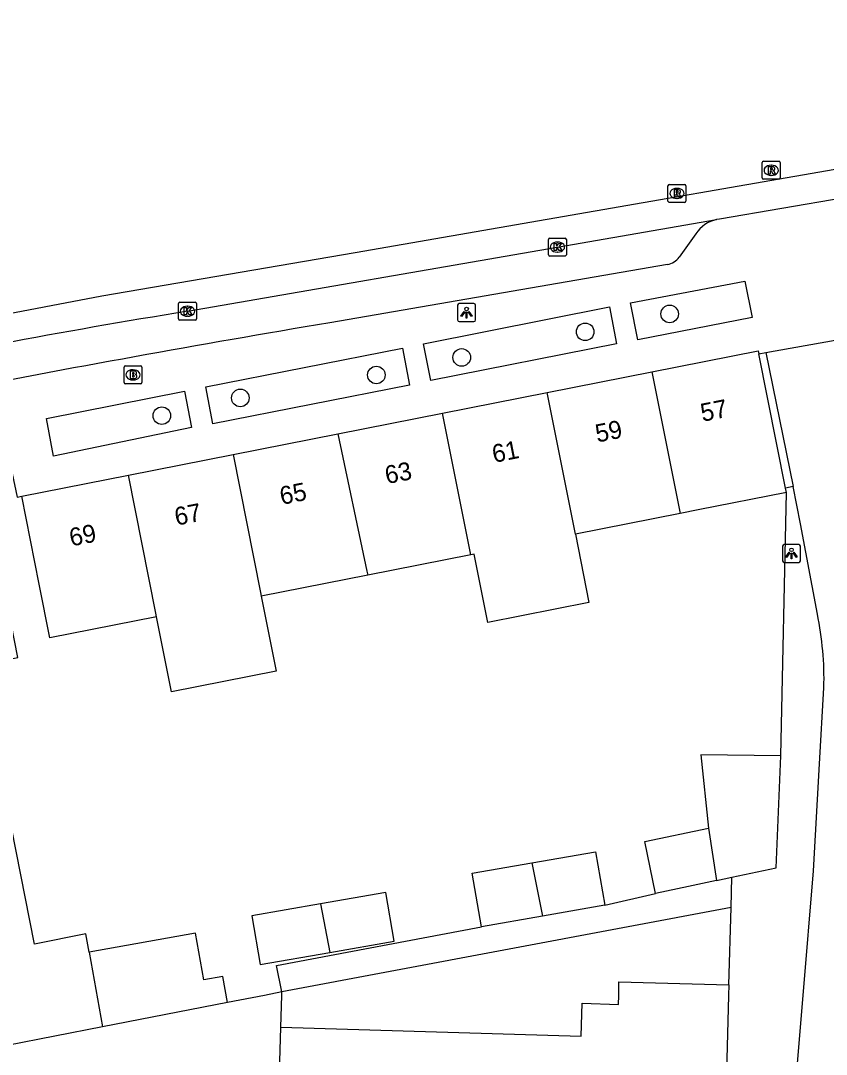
# Model space of a CAD drawing. Extents: x 159053 to 160041, y 380450 to 381422.
# Drawn here: x 159374 to 159418.9, y 381246.7 to 381304.3 of the extents above; entities that cross this region are included whole.
import ezdxf

# ---------------------------------------------------------------- set-up
doc = ezdxf.new("R2010")
doc.units = 0
for name, color, linetype in [('IMGEO_Boom', 7, 'Continuous'), ('IMGEO_Brandkraan', 7, 'Continuous'), ('IMGEO_Kolk', 7, 'Continuous'), ('IMGEO_Lichtpunt', 7, 'Continuous'), ('IMGEO_Muur', 7, 'Continuous'), ('IMGEO_Pand', 7, 'Continuous'), ('IMGEO_Pand_nummerreeks', 7, 'Continuous'), ('IMGEO_Rijbaan_lokaal_gesloten', 7, 'Continuous'), ('IMGEO_Rijbaan_lokaal_open', 7, 'Continuous'), ('IMGEO_Rioolput', 7, 'Continuous'), ('IMGEO_Voetpad_open', 7, 'Continuous')]:
    doc.layers.add(name, color=color, linetype=linetype)

msp = doc.modelspace()

# ---------------------------------------------------------------- linework, layer by layer
at = {"layer": 'IMGEO_Boom'}
for centre in [(159410.139, 381287.939), (159405.431, 381286.943), (159398.564, 381285.517), (159393.813, 381284.541), (159386.237, 381283.263), (159381.873, 381282.275)]:
    msp.add_circle(centre, 0.489, dxfattribs=at)
at = {"layer": 'IMGEO_Brandkraan'}
for p, q in [((159379.765, 381284.122), (159379.765, 381284.974)), ((159379.84, 381285.048), (159380.692, 381285.048)), ((159380.766, 381284.974), (159380.766, 381284.122)), ((159380.253, 381284.828), (159380.278, 381284.828)), ((159380.692, 381284.048), (159379.84, 381284.048)), ((159380.276, 381284.268), (159380.251, 381284.268))]:
    msp.add_line(p, q, dxfattribs=at)
for points in [[(159379.765, 381284.122), (159379.765, 381284.974)], [(159379.84, 381285.048), (159380.692, 381285.048)], [(159380.766, 381284.974), (159380.766, 381284.122)], [(159380.113, 381284.748), (159380.113, 381284.348), (159380.326, 381284.348)], [(159380.344, 381284.748), (159380.113, 381284.748)], [(159380.292, 381284.667), (159380.238, 381284.667), (159380.238, 381284.591)], [(159380.238, 381284.591), (159380.291, 381284.591)], [(159380.3, 381284.515), (159380.238, 381284.515), (159380.238, 381284.434)], [(159380.238, 381284.434), (159380.3, 381284.434)], [(159380.692, 381284.048), (159379.84, 381284.048)]]:
    msp.add_lwpolyline(points, dxfattribs=at)
for centre, radius, start, end in [((159379.842, 381284.972), 0.0765, 91.55205, 178.44795), ((159379.842, 381284.972), 0.0765, 91.55205, 178.44795), ((159380.69, 381284.972), 0.0765, 1.55205, 88.44795), ((159380.69, 381284.972), 0.0765, 1.55205, 88.44795), ((159380.293, 381284.629), 0.0379, 267.82845, 90.93552), ((159380.301, 381284.474), 0.0404, 269.87594, 90.50774), ((159380.332, 381284.599), 0.251, 268.66757, 293.53466), ((159380.348, 381284.603), 0.145, 59.4692, 91.53667), ((159380.373, 381284.65), 0.0922, 285.51372, 58.15012), ((159380.378, 381284.458), 0.105, 301.31148, 78.98903), ((159379.842, 381284.124), 0.0765, 181.55205, 268.44795), ((159379.842, 381284.124), 0.0765, 181.55205, 268.44795), ((159380.69, 381284.124), 0.0765, 271.55205, 358.44795), ((159380.69, 381284.124), 0.0765, 271.55205, 358.44795)]:
    msp.add_arc(centre, radius, start, end, dxfattribs=at)
for centre, major_axis, ratio, start_param, end_param in [((159380.252, 381284.548), (-0.387, 0.002), 0.722429, 4.712389, 7.853982), ((159380.277, 381284.548), (-0.39, 0.002), 0.717154, 1.570796, 4.712389)]:
    msp.add_ellipse(centre, major_axis=major_axis, ratio=ratio, start_param=start_param, end_param=end_param, dxfattribs=at)
at = {"layer": 'IMGEO_Kolk'}
for p, q in [((159403.387, 381291.236), (159403.387, 381292.088)), ((159403.462, 381292.162), (159404.314, 381292.162)), ((159403.875, 381291.942), (159403.9, 381291.942)), ((159404.388, 381292.088), (159404.388, 381291.236)), ((159403.898, 381291.382), (159403.873, 381291.382)), ((159404.314, 381291.162), (159403.462, 381291.162)), ((159382.799, 381287.662), (159382.799, 381288.514)), ((159382.874, 381288.588), (159383.726, 381288.588)), ((159383.287, 381288.368), (159383.312, 381288.368)), ((159383.8, 381288.514), (159383.8, 381287.662)), ((159383.31, 381287.808), (159383.285, 381287.808)), ((159383.726, 381287.588), (159382.874, 381287.588))]:
    msp.add_line(p, q, dxfattribs=at)
for points in [[(159403.387, 381291.236), (159403.387, 381292.088)], [(159403.462, 381292.162), (159404.314, 381292.162)], [(159403.708, 381291.862), (159403.831, 381291.862), (159403.831, 381291.711), (159403.961, 381291.862), (159404.125, 381291.862), (159403.979, 381291.711), (159404.132, 381291.462), (159403.98, 381291.462), (159403.895, 381291.626), (159403.831, 381291.559), (159403.831, 381291.462), (159403.708, 381291.462), (159403.708, 381291.862)], [(159404.388, 381292.088), (159404.388, 381291.236)], [(159404.314, 381291.162), (159403.462, 381291.162)], [(159382.799, 381287.662), (159382.799, 381288.514)], [(159382.874, 381288.588), (159383.726, 381288.588)], [(159383.8, 381288.514), (159383.8, 381287.662)], [(159383.12, 381288.288), (159383.243, 381288.288), (159383.243, 381288.137), (159383.373, 381288.288), (159383.537, 381288.288), (159383.391, 381288.137), (159383.544, 381287.888), (159383.392, 381287.888), (159383.307, 381288.052), (159383.243, 381287.985), (159383.243, 381287.888), (159383.12, 381287.888), (159383.12, 381288.288)], [(159383.726, 381287.588), (159382.874, 381287.588)]]:
    msp.add_lwpolyline(points, dxfattribs=at)
for centre, start, end in [((159403.464, 381292.086), 91.55205, 178.44795), ((159403.464, 381292.086), 91.55205, 178.44795), ((159404.312, 381292.086), 1.55205, 88.44795), ((159404.312, 381292.086), 1.55205, 88.44795), ((159403.464, 381291.238), 181.55205, 268.44795), ((159403.464, 381291.238), 181.55205, 268.44795), ((159404.312, 381291.238), 271.55205, 358.44795), ((159404.312, 381291.238), 271.55205, 358.44795), ((159382.876, 381288.512), 91.55205, 178.44795), ((159382.876, 381288.512), 91.55205, 178.44795), ((159383.724, 381288.512), 1.55205, 88.44795), ((159383.724, 381288.512), 1.55205, 88.44795), ((159382.876, 381287.664), 181.55205, 268.44795), ((159382.876, 381287.664), 181.55205, 268.44795), ((159383.724, 381287.664), 271.55205, 358.44795), ((159383.724, 381287.664), 271.55205, 358.44795)]:
    msp.add_arc(centre, 0.0765, start, end, dxfattribs=at)
for centre, major_axis, ratio, start_param, end_param in [((159403.874, 381291.662), (-0.387, 0.002), 0.722429, 4.712389, 7.853982), ((159403.899, 381291.662), (-0.39, 0.002), 0.717154, 1.570796, 4.712389), ((159383.286, 381288.088), (-0.387, 0.002), 0.722429, 4.712389, 7.853982), ((159383.311, 381288.088), (-0.39, 0.002), 0.717154, 1.570796, 4.712389)]:
    msp.add_ellipse(centre, major_axis=major_axis, ratio=ratio, start_param=start_param, end_param=end_param, dxfattribs=at)
at = {"layer": 'IMGEO_Lichtpunt'}
for p, q in [((159398.333, 381288.418), (159398.333, 381287.611)), ((159398.333, 381288.418), (159398.333, 381287.611)), ((159399.235, 381288.513), (159398.427, 381288.513)), ((159399.235, 381288.513), (159398.427, 381288.513)), ((159399.329, 381287.611), (159399.329, 381288.418)), ((159399.329, 381287.611), (159399.329, 381288.418)), ((159398.427, 381287.517), (159399.235, 381287.517)), ((159398.427, 381287.517), (159399.235, 381287.517)), ((159417.32, 381275.102), (159416.512, 381275.102)), ((159417.32, 381275.102), (159416.512, 381275.102)), ((159416.418, 381275.007), (159416.418, 381274.2)), ((159416.418, 381275.007), (159416.418, 381274.2)), ((159417.414, 381274.2), (159417.414, 381275.007)), ((159417.414, 381274.2), (159417.414, 381275.007)), ((159416.512, 381274.106), (159417.32, 381274.106)), ((159416.512, 381274.106), (159417.32, 381274.106))]:
    msp.add_line(p, q, dxfattribs=at)
for points in [[(159398.707, 381288.082), (159398.746, 381288.054), (159398.558, 381287.792), (159398.52, 381287.819), (159398.707, 381288.082)], [(159398.809, 381288.034), (159398.856, 381288.034), (159398.856, 381287.712), (159398.809, 381287.712), (159398.809, 381288.034)], [(159398.919, 381288.054), (159398.957, 381288.081), (159399.144, 381287.819), (159399.105, 381287.791), (159398.919, 381288.054)], [(159416.792, 381274.671), (159416.831, 381274.643), (159416.643, 381274.381), (159416.605, 381274.408), (159416.792, 381274.671)], [(159416.894, 381274.623), (159416.941, 381274.623), (159416.941, 381274.301), (159416.894, 381274.301), (159416.894, 381274.623)], [(159417.004, 381274.643), (159417.042, 381274.67), (159417.229, 381274.408), (159417.19, 381274.38), (159417.004, 381274.643)]]:
    msp.add_lwpolyline(points, dxfattribs=at)
for centre in [(159398.832, 381288.216), (159416.917, 381274.805)]:
    msp.add_circle(centre, 0.0994, dxfattribs=at)
for centre, start, end in [((159398.427, 381288.418), 90, 180), ((159398.427, 381288.418), 90, 180), ((159399.235, 381288.418), 0, 90), ((159399.235, 381288.418), 0, 90), ((159398.427, 381287.611), 180, 270), ((159398.427, 381287.611), 180, 270), ((159399.235, 381287.611), 270, 0), ((159399.235, 381287.611), 270, 360), ((159416.512, 381275.007), 90, 180), ((159416.512, 381275.007), 90, 180), ((159417.32, 381275.007), 0, 90), ((159417.32, 381275.007), 0, 90), ((159416.512, 381274.2), 180, 270), ((159416.512, 381274.2), 180, 270), ((159417.32, 381274.2), 270, 0), ((159417.32, 381274.2), 270, 360)]:
    msp.add_arc(centre, 0.0946, start, end, dxfattribs=at)
at = {"layer": 'IMGEO_Muur'}
msp.add_lwpolyline([(159416.32, 381263.335), (159416.632, 381278.003)], dxfattribs=at)
at = {"layer": 'IMGEO_Pand'}
for points in [[(159409.148, 381284.721), (159415.064, 381285.89), (159415.097, 381285.726)], [(159416.585, 381278.242), (159415.097, 381285.726)], [(159403.321, 381283.569), (159409.148, 381284.721)], [(159409.148, 381284.721), (159410.715, 381276.828)], [(159397.494, 381282.418), (159403.321, 381283.569)], [(159404.888, 381275.677), (159403.321, 381283.569)], [(159391.666, 381281.266), (159397.494, 381282.418)], [(159399.061, 381274.527), (159397.494, 381282.418)], [(159385.839, 381280.115), (159391.666, 381281.266)], [(159391.666, 381281.266), (159393.287, 381273.614), (159393.33, 381273.395)], [(159380.012, 381278.963), (159385.839, 381280.115)], [(159385.839, 381280.115), (159387.363, 381272.438), (159387.404, 381272.225)], [(159374.075, 381277.79), (159380.012, 381278.963)], [(159381.578, 381271.075), (159381.537, 381271.281), (159380.012, 381278.963)], [(159416.632, 381278.003), (159411.728, 381277.028), (159410.715, 381276.828)], [(159416.632, 381278.003), (159416.585, 381278.242)], [(159377.823, 381252.401), (159377.639, 381253.422), (159374.787, 381252.855), (159371.7, 381268.379), (159373.857, 381268.808), (159373.123, 381272.499), (159372.148, 381277.402), (159367.434, 381276.5)], [(159381.578, 381271.075), (159375.643, 381269.903), (159375.05, 381272.886), (159374.075, 381277.79)], [(159410.715, 381276.828), (159404.888, 381275.677)], [(159404.888, 381275.677), (159405.64, 381271.866), (159400.014, 381270.755), (159399.262, 381274.567), (159399.061, 381274.527)], [(159399.061, 381274.527), (159393.33, 381273.395)], [(159393.33, 381273.395), (159387.404, 381272.225)], [(159387.404, 381272.225), (159388.233, 381268.058), (159382.405, 381266.907), (159381.578, 381271.075)], [(159416.32, 381263.335), (159411.867, 381263.389), (159412.301, 381259.31)], [(159413.601, 381256.573), (159416.072, 381257.095), (159416.32, 381263.335)], [(159409.357, 381255.675), (159408.747, 381258.559), (159412.301, 381259.31)], [(159412.301, 381259.31), (159412.745, 381256.392)], [(159402.467, 381257.377), (159406.005, 381257.997), (159406.526, 381255.023)], [(159399.663, 381253.82), (159399.142, 381256.795), (159402.467, 381257.377)], [(159402.467, 381257.377), (159403.055, 381254.414)], [(159412.745, 381256.392), (159411.181, 381256.061), (159409.357, 381255.675)], [(159412.745, 381256.392), (159413.601, 381256.573)], [(159391.214, 381252.389), (159394.808, 381253.018), (159394.334, 381255.73), (159390.693, 381255.093)], [(159390.693, 381255.093), (159386.878, 381254.424), (159387.353, 381251.713), (159391.214, 381252.389)], [(159390.693, 381255.093), (159391.214, 381252.389)], [(159406.526, 381255.023), (159403.055, 381254.414)], [(159403.055, 381254.414), (159399.663, 381253.82)], [(159385.535, 381249.6), (159385.272, 381251.054), (159384.217, 381250.863), (159383.746, 381253.471), (159377.823, 381252.401)], [(159377.823, 381252.401), (159378.574, 381248.24)], [(159388.493, 381248.223), (159405.205, 381247.729), (159405.259, 381249.561), (159407.292, 381249.501), (159407.3, 381250), (159407.312, 381250.751), (159413.435, 381250.58)], [(159413.435, 381250.58), (159413.419, 381250), (159413.184, 381241.507), (159413.175, 381241.164)], [(159388.557, 381250.19), (159387.584, 381250), (159385.535, 381249.6)], [(159388.493, 381248.223), (159388.551, 381250), (159388.557, 381250.19)], [(159385.535, 381249.6), (159378.574, 381248.24)], [(159378.574, 381248.24), (159373.269, 381247.204)], [(159388.306, 381241.899), (159388.493, 381248.223)]]:
    msp.add_lwpolyline(points, dxfattribs=at)
at = {"layer": 'IMGEO_Rijbaan_lokaal_gesloten'}
for points in [[(159240.511, 381248.03), (159239.894, 381249.365), (159249.857, 381253.978), (159259.538, 381258.444), (159265.788, 381261.312), (159272.321, 381263.757), (159279.511, 381266.107), (159286.044, 381267.988), (159291.683, 381269.587), (159298.874, 381271.561), (159312.832, 381274.758), (159333.98, 381279.647), (159349.677, 381283.267), (159365.28, 381286.417), (159378.533, 381288.955), (159392.632, 381291.353), (159430.464, 381297.936), (159461.669, 381303.342), (159467.508, 381304.266)], [(159420.34, 381294.51), (159419.841, 381294.411), (159412.902, 381293.217), (159412.749, 381293.191)], [(159383.296, 381288.089), (159403.884, 381291.663), (159412.749, 381293.191)]]:
    msp.add_lwpolyline(points, dxfattribs=at)
msp.add_arc((159448.885, 380882.783), 410.578, 99.19224, 102.13455, dxfattribs=at)
at = {"layer": 'IMGEO_Rijbaan_lokaal_open'}
for points in [[(159415.481, 381285.794), (159420.183, 381286.629)], [(159415.481, 381285.794), (159417.005, 381278.325)], [(159418.357, 381271.232), (159417.428, 381276.254), (159417.005, 381278.325)], [(159414.968, 381214.908), (159414.999, 381215.304), (159416.349, 381234.665), (159416.645, 381238.911), (159416.846, 381241.338), (159417.564, 381250), (159418.138, 381256.93), (159418.471, 381262.899), (159418.719, 381267.127)]]:
    msp.add_lwpolyline(points, dxfattribs=at)
msp.add_arc((159401.044, 381267.637), 17.683, 358.34799, 11.73121, dxfattribs=at)
at = {"layer": 'IMGEO_Rioolput'}
for p, q in [((159415.364, 381296.435), (159416.216, 381296.435)), ((159415.289, 381295.509), (159415.289, 381296.361)), ((159415.777, 381296.215), (159415.802, 381296.215)), ((159416.29, 381296.361), (159416.29, 381295.509)), ((159416.216, 381295.435), (159415.364, 381295.435)), ((159415.8, 381295.655), (159415.775, 381295.655)), ((159410.043, 381294.225), (159410.043, 381295.077)), ((159410.118, 381295.151), (159410.97, 381295.151)), ((159410.531, 381294.931), (159410.556, 381294.931)), ((159411.044, 381295.077), (159411.044, 381294.225)), ((159410.97, 381294.151), (159410.118, 381294.151)), ((159410.554, 381294.371), (159410.529, 381294.371))]:
    msp.add_line(p, q, dxfattribs=at)
for points in [[(159415.364, 381296.435), (159416.216, 381296.435)], [(159415.289, 381295.509), (159415.289, 381296.361)], [(159415.878, 381296.133), (159415.626, 381296.135), (159415.626, 381295.735)], [(159415.626, 381295.735), (159415.75, 381295.735), (159415.75, 381295.897), (159415.761, 381295.897)], [(159415.804, 381296.054), (159415.75, 381296.054), (159415.75, 381295.973)], [(159415.75, 381295.973), (159415.802, 381295.973)], [(159415.808, 381295.868), (159415.879, 381295.735), (159416.019, 381295.735), (159415.954, 381295.861)], [(159416.29, 381296.361), (159416.29, 381295.509)], [(159416.216, 381295.435), (159415.364, 381295.435)], [(159410.043, 381294.225), (159410.043, 381295.077)], [(159410.118, 381295.151), (159410.97, 381295.151)], [(159410.632, 381294.849), (159410.38, 381294.851), (159410.38, 381294.451)], [(159410.558, 381294.77), (159410.504, 381294.77), (159410.504, 381294.689)], [(159410.504, 381294.689), (159410.556, 381294.689)], [(159411.044, 381295.077), (159411.044, 381294.225)], [(159410.97, 381294.151), (159410.118, 381294.151)], [(159410.38, 381294.451), (159410.504, 381294.451), (159410.504, 381294.613), (159410.515, 381294.613)], [(159410.562, 381294.584), (159410.633, 381294.451), (159410.773, 381294.451), (159410.708, 381294.577)]]:
    msp.add_lwpolyline(points, dxfattribs=at)
for centre, radius, start, end in [((159415.366, 381296.359), 0.0765, 91.55205, 178.44795), ((159415.366, 381296.359), 0.0765, 91.55205, 178.44795), ((159416.214, 381296.359), 0.0765, 1.55205, 88.44795), ((159416.214, 381296.359), 0.0765, 1.55205, 88.44795), ((159415.76, 381295.844), 0.0533, 26.02933, 88.69889), ((159415.786, 381296.162), 0.19, 274.7715, 282.96867), ((159415.81, 381295.958), 0.0964, 77.00612, 93.18647), ((159415.824, 381296.015), 0.0378, 276.66336, 79.67722), ((159415.877, 381296.023), 0.109, 350.36119, 89.41601), ((159415.875, 381296.023), 0.112, 277.58423, 350.98172), ((159415.859, 381295.808), 0.108, 29.51342, 73.79051), ((159415.366, 381295.511), 0.0765, 181.55205, 268.44795), ((159415.366, 381295.511), 0.0765, 181.55205, 268.44795), ((159416.214, 381295.511), 0.0765, 271.55205, 358.44795), ((159416.214, 381295.511), 0.0765, 271.55205, 358.44795), ((159410.12, 381295.075), 0.0765, 91.55205, 178.44795), ((159410.12, 381295.075), 0.0765, 91.55205, 178.44795), ((159410.54, 381294.878), 0.19, 274.7715, 282.96867), ((159410.564, 381294.674), 0.0964, 77.00612, 93.18647), ((159410.578, 381294.731), 0.0378, 276.66336, 79.67722), ((159410.631, 381294.739), 0.109, 350.36119, 89.41601), ((159410.629, 381294.739), 0.112, 277.58423, 350.98172), ((159410.968, 381295.075), 0.0765, 1.55205, 88.44795), ((159410.968, 381295.075), 0.0765, 1.55205, 88.44795), ((159410.12, 381294.227), 0.0765, 181.55205, 268.44795), ((159410.12, 381294.227), 0.0765, 181.55205, 268.44795), ((159410.514, 381294.56), 0.0533, 26.02933, 88.69889), ((159410.613, 381294.524), 0.108, 29.51342, 73.79051), ((159410.968, 381294.227), 0.0765, 271.55205, 358.44795), ((159410.968, 381294.227), 0.0765, 271.55205, 358.44795)]:
    msp.add_arc(centre, radius, start, end, dxfattribs=at)
for centre, major_axis, ratio, start_param, end_param in [((159415.776, 381295.935), (-0.387, 0.002), 0.722429, 4.712389, 7.853982), ((159415.801, 381295.935), (-0.39, 0.002), 0.717154, 1.570796, 4.712389), ((159410.53, 381294.651), (-0.387, 0.002), 0.722429, 4.712389, 7.853982), ((159410.555, 381294.651), (-0.39, 0.002), 0.717154, 1.570796, 4.712389)]:
    msp.add_ellipse(centre, major_axis=major_axis, ratio=ratio, start_param=start_param, end_param=end_param, dxfattribs=at)
at = {"layer": 'IMGEO_Voetpad_open'}
for points in [[(159411.598, 381292.405), (159410.674, 381291.103)], [(159410.014, 381290.696), (159391.213, 381287.445)], [(159414.32, 381289.758), (159414.721, 381287.745), (159408.364, 381286.49), (159407.957, 381288.554), (159414.32, 381289.758)], [(159407.169, 381286.272), (159396.834, 381284.224), (159396.426, 381286.266), (159406.787, 381288.335), (159407.169, 381286.272)], [(159395.654, 381283.978), (159384.706, 381281.825), (159384.327, 381283.885), (159395.257, 381286.034), (159395.654, 381283.978)], [(159415.097, 381285.726), (159415.481, 381285.794)], [(159383.528, 381281.609), (159375.846, 381280.027), (159375.449, 381282.123), (159383.129, 381283.647), (159383.528, 381281.609)], [(159329.274, 381268.861), (159328.524, 381272.219), (159348.239, 381276.226), (159348.106, 381276.85), (159361.621, 381279.542), (159372.748, 381281.64), (159372.989, 381281.685), (159373.821, 381277.736), (159374.075, 381277.79)], [(159416.32, 381263.335), (159416.632, 381278.003)], [(159417.005, 381278.325), (159416.585, 381278.242)], [(159413.554, 381254.89), (159413.601, 381256.573)], [(159406.526, 381255.023), (159409.357, 381255.675)], [(159413.554, 381254.89), (159388.557, 381250.19)], [(159413.435, 381250.58), (159413.554, 381254.89)], [(159388.557, 381250.19), (159388.25, 381251.66), (159399.663, 381253.82)]]:
    msp.add_lwpolyline(points, dxfattribs=at)
for centre, radius, start, end in [((159413.145, 381291.376), 1.858, 102.30131, 146.35581), ((159409.834, 381291.726), 1.046, 279.9005, 323.421), ((159523.613, 380495.628), 802.81, 99.492613, 101.066417)]:
    msp.add_arc(centre, radius, start, end, dxfattribs=at)

# ---------------------------------------------------------------- texts
at = {"layer": 'IMGEO_Pand_nummerreeks'}
for s, rotation, p in [('57', 11.17842, (159411.961, 381281.933)), ('59', 11.17842, (159406.106, 381280.776)), ('61', 11.17841, (159400.36, 381279.641)), ('63', 11.17842, (159394.395, 381278.462)), ('65', 11.17842, (159388.539, 381277.305)), ('67', 11.17842, (159382.684, 381276.148)), ('69', 11.17842, (159376.828, 381274.991))]:
    msp.add_text(s, height=1, rotation=rotation, dxfattribs=at).set_placement(p)

doc.saveas('drawing.dxf')
